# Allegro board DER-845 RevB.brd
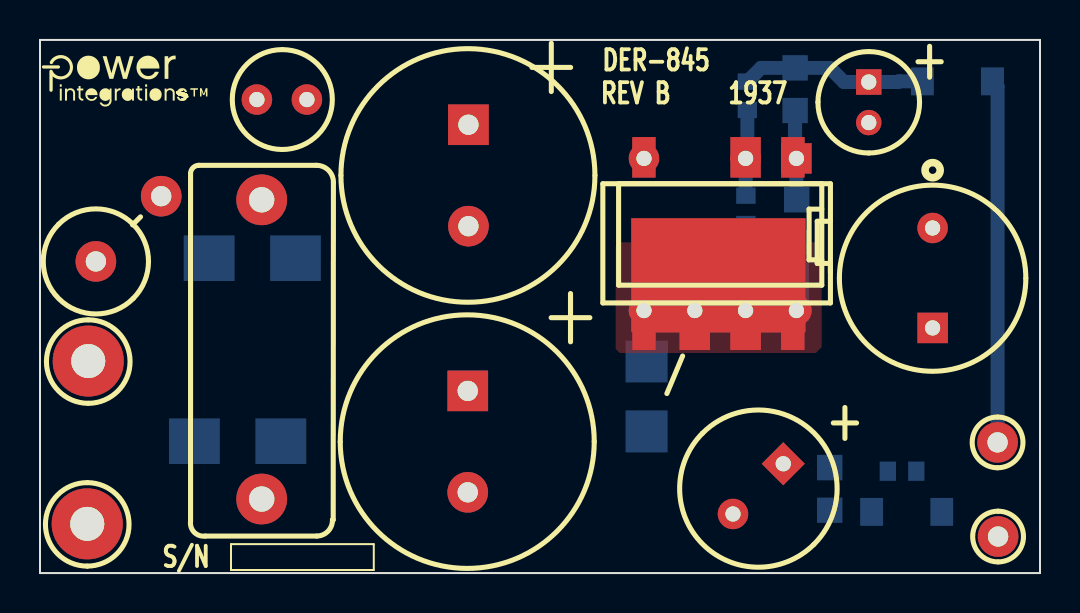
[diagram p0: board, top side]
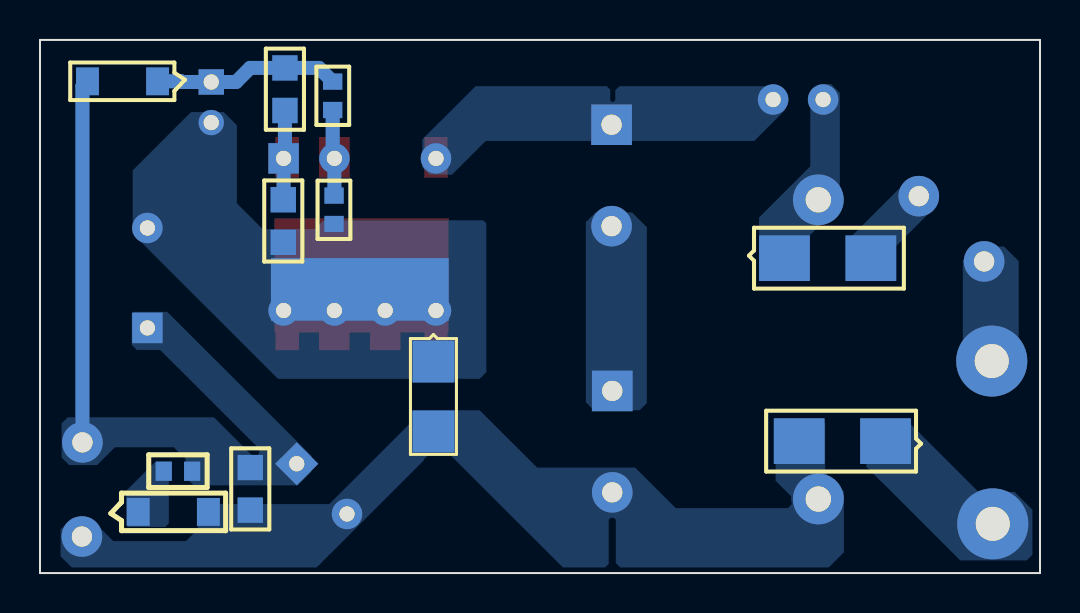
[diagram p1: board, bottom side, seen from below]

Outline 50 x 26.7 mm; copper layers: TOP, BOTTOM. Coordinates in mm from the lower left corner of the outline.
Outline path: 0,26.7 0,0 50,0 50,26.7 0,26.7

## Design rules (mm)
constraint set DEFAULT: min track width 0.508

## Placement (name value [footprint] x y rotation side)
C1  150 nF  [PI_NP_CAPRAD709X276LS590D050]  11.08 18.69 270 top
C2  47 uF  [PIPOLCAPCLYD500LS200040]  21.42 22.45 270 top
C3  100 nF  [PISMC0805]  37.84 18.7 270 bottom
C4  10 uF  [PIPOLCAPCLYD200LS80030]  41.44 24.59 270 top
C5  220 uF  [PIPOLCAPCLYD320LS140030]  37.16 5.47 225 top
C7  47 uF  [PIPOLCAPCLYD500LS200040]  21.39 9.12 270 top
D1  GS1M-LTP  [PISMDO214AC12]  12.78 15.77 180 bottom
D2  GS1M-LTP  [PISMDO214AC12]  7.72 6.61 0 bottom
D4  RS1MWF-7  [PI_SM_SOD-123_12]  44.12 24.63 0 bottom
D5  CD1408-FU1800  [PISMD1408]  30.33 10.59 270 bottom
GND  BLK  [PITPKEYSTONE100X100]  47.9 1.83 0 top
L  WHT  [PITPKEYSTONE125X125]  2.41 10.62 0 top
L1  1000 uH  [PICHOKETOKINVD216H413LS098D030]  10.85 23.71 0 top
L2  1.2 mH  [PI_CHOKE_RL5480-3_D2]  44.63 12.28 90 top
N  BLK  [PITPKEYSTONE125X125]  2.36 2.46 0 top
NOREF  -  []  -0.46 25.83 0 top
NOREF#2  -  []  0 26.7 0 top
NOREF#3  -  []  50 0 90 top
R1  2.74 k  [PISMR0603]  35.3 18.9 270 bottom
R2  18.2 k  [PISMR0603]  35.37 23.19 90 bottom
R3  35.7 k  [PISMR0805]  37.75 23.17 90 bottom
R4  24.9 k  [PISMR0805]  39.49 5.28 270 bottom
R5  499  [PISMR0603]  42.39 5.1 0 bottom
RF1  8.2  [PI2WRESD200LS725D040]  2.79 15.61 45 top
U1  LNK3296G  [PIICSMD8CSHORT5678IPC]  37.64 20.82 180 top
U2  LNK3296P  [PIICDIP8CSHORT5678]  37.82 20.77 180 top
UNK+V  RED  [PITPKEYSTONE100X100]  47.88 6.54 0 top
VR1  MMSZ5243BT1G  [PI_SM_SOD-123_12]  45.09 3.06 180 bottom

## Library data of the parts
C1 C3 = CAP NP
C2 C7 = CAP POL: alternate symbols: (pipolcapclyd500ls2000401200lh)
C4 = CAP POL: alternate symbols: (pipolcapclyd200ls80030h)
C5 = CAP POL: alternate symbols: (pipolcapclyd320ls140030430h)
D1 D2 D5 = DIODE
D4 = DIODE: alternate symbols: (pi_sm_sod-123_12_1)
GND L N UNK+V = TESTPOINT
L1 = INDUCTOR
L2 = INDUCTOR_DOT2: alternate symbols: (pi_choke_RL5480-3H_d2)
R1-R5 = R
RF1 = RF: alternate symbols: (pi2wresd200ls900d040,pi2wvresd200ls300d040,pi2wvresd200ls400d040,pi2wvresd180ls250d040,pi2wvresd180ls200d040)
U1 = LNK32XX_8C: alternate symbols: (piicsmd8cshort5678)
U2 = LNK32XX_8C
VR1 = DIODE_ZENER

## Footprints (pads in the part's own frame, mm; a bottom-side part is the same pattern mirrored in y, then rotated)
PI2WRESD200LS725D040
  round 2.032 hole 1.016: 1(0,0) 2(4.62,0)
PI_CHOKE_RL5480-3_D2
  rect 1.524x1.524 hole 0.762: 1(0,0)
  round 1.524 hole 0.762: 2(5.004,0)
PI_NP_CAPRAD709X276LS590D050
  round 2.54 hole 1.27: 1(0,0) 2(14.986,0)
PI_SM_SOD-123_12
  rect 1.143x1.397 smd: 1(0,0) 2(3.505,0)
PICHOKETOKINVD216H413LS098D030
  round 1.524 hole 0.762: 1(0,0) 2(2.5,0)
PIICDIP8CSHORT5678
  rect 1.524x1.524 hole 0.762: 1(0,0)
  round 1.524 hole 0.762: 2(2.54,0) 4(7.62,0) 5(7.62,7.62) 6(5.08,7.62) 7(2.54,7.62) 8(0,7.62)
PIICSMD8CSHORT5678IPC
  rect 1.168x2.032 smd: 1(0,0) 4(7.442,0) 5(7.442,8.636) 8(0,8.636)
  rect 1.524x2.032 smd: 2(2.362,0) 6(4.902,8.636) 7(2.362,8.636)
PIPOLCAPCLYD200LS80030
  rect 1.27x1.27 hole 0.762: 1(0,0)
  round 1.27 hole 0.762: 2(2.032,0)
PIPOLCAPCLYD320LS140030
  rect 1.524x1.524 hole 0.762: 1(0,0)
  round 1.524 hole 0.762: 2(3.556,0)
PIPOLCAPCLYD500LS200040
  rect 2.032x2.032 hole 1.016: 1(0,0)
  round 2.032 hole 1.016: 2(5.08,0)
PISMC0805
  rect 1.27x1.27 smd: 1(0,0) 2(2.134,0)
PISMD1408
  rect 2.1x2.1 smd: 1(0,0) 2(3.5,0)
PISMDO214AC12
  rect 2.54x2.286 smd: 1(0,0) 2(4.318,0)
PISMR0603
  rect 0.813x0.965 smd: 1(0,0) 2(1.422,0)
PISMR0805
  rect 1.27x1.27 smd: 1(0,0) 2(2.134,0)
PITPKEYSTONE100X100
  round 2.032 hole 1.016: 1(0,0)
PITPKEYSTONE125X125
  round 3.556 hole 1.702: 1(0,0)

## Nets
SOURCE: C3.2 C4.2 D5.1 L2.2 R1.2 U1.5(S) U1.6 U1.7 U1.8 U2.5(S) U2.6 U2.7 U2.8
N109644: C1.1 D1.1 L1.1
N109746: C2.1 L1.2 U1.4 U2.4
N109826: C1.2 C5.2 C7.2 D2.2 D5.2 GND.1 R4.2 VR1.2
N110802: C3.1 R3.1 U1.1 U2.1
N111146: R1.1 R2.1 U1.2 U2.2
N111959: C5.1 D4.2 L2.1 R4.1 R5.1 UNK+V.1
N118115: D1.2 RF1.2
N118119: L.1 RF1.1
N4132044: C4.1 D4.1 R2.2 R3.2
N4143200: D2.1 N.1
N4148852: C2.2 C7.1
N4178876: R5.2 VR1.1

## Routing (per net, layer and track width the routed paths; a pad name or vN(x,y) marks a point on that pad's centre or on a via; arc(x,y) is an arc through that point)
N110802: length 4.5
  BOTTOM w0.7: C3.1 37.82,18.71 U2.1 37.75,20.83 R3.1
N111146: length 4.3
  BOTTOM w0.7: R2.1 35.37,20.85 U2.2 35.28,18.92 R1.1
N111959: length 18.2
  BOTTOM w0.7: UNK+V.1 47.88,24.38 D4.2
N4132044: length 9.3
  BOTTOM w0.7: D4.1 42.95,24.63 42.91,24.59 C4.1 40.2,24.59 39.49,25.3 R3.2 36.05,25.3 R2.2

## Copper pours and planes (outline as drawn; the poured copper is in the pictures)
SOURCE on TOP (solid shape): 38.28,12.06 29.56,12.06 29.56,17.77 38.28,17.77
SOURCE on BOTTOM (solid shape): 38.45,12.64 29.56,12.64 29.56,15.77 38.45,15.77
SOURCE on TOP: 38.76,16.56 29.01,16.56 28.78,16.33 28.78,11.23 28.98,11.02 38.79,11.02 39.09,11.33 39.09,16.23
SOURCE on BOTTOM: 38.1,9.73 28.02,9.73 27.69,10.06 27.69,17.51 27.84,17.67 35.81,17.67 36.26,17.22 38.86,17.22 40.16,18.52 40.16,22.43 40.82,23.09 42.44,23.09 45.36,20.17 45.36,16.99
N109644 on BOTTOM: 11.48,24 11.48,20.37 14.05,17.81 14.05,14.91 11.99,14.91 11.66,15.24 11.66,16.76 10.29,18.14 10.24,18.14 10.01,18.36 10.01,24.05 10.44,24.49 11,24.49
N109746 on BOTTOM: 14.29,21.64 27.71,21.64 29.4,19.95 30.52,19.95 30.89,20.32 30.89,21.72 28.22,24.38 21.67,24.38 21.49,24.21 21.49,23.67 21.41,23.6 21.34,23.6 21.23,23.7 21.23,24.18 21.03,24.38 13.03,24.38 12.76,24.12 12.76,23.16
N109826 on BOTTOM: 10.57,0.28 20.98,0.28 21.21,0.51 21.21,2.67 21.31,2.77 21.46,2.77 21.56,2.67 21.56,0.46 21.74,0.28 23.85,0.28 29.44,5.87 30.63,5.87 30.81,5.69 30.81,5.64 36.17,0.28 48.41,0.28 48.97,0.84 48.97,2.18 48.39,2.77 47.5,2.77 46.33,1.6 42.7,1.6 42.11,2.18 42.11,3.17 41.83,3.45 35.53,3.45 31.34,7.65 31.34,8.15 28.02,8.15 25.15,5.28 20.24,5.28 18.21,3.25 12.6,3.25 12.42,3.43 12.42,3.58 12.45,3.61 12.45,3.85 13.22,4.62 13.22,7.3 12.8,7.72 10.95,7.72 10.74,7.52 10.74,5.03 9.8,4.09 9.8,1.04
N111959 on BOTTOM: 36.42,5.87 36.42,5.08 37.11,4.39 42.32,4.39 42.72,4.8 42.72,5.71 43.31,6.3 46.25,6.3 47.14,5.41 48.54,5.41 48.92,5.79 48.92,7.49 48.62,7.8 41.3,7.8 39.4,5.89 39.14,5.89 39.04,5.99 39.04,6.22 43.99,11.18 45.16,11.18 45.42,11.43 45.42,13 45.34,13.08 43.64,13.08
N118115 on BOTTOM: 5.51,19.53 5.51,18.06 7.25,16.32 7.25,15.3 7.82,14.73 9.37,14.73 9.5,14.86 9.5,16.79 6.63,19.66 5.64,19.66
N118119 on BOTTOM: 3.17,16.36 1.8,16.36 1.07,15.62 1.07,9.86 1.88,9.04 3.2,9.04 3.86,9.7 3.86,15.67
N4143200 on BOTTOM: 3.99,0.64 0.66,0.64 0.38,0.91 0.38,3.17 1.27,4.06 3.07,4.06 6.65,7.65 8.46,7.65 8.69,7.42 8.69,5.33
N4148852 on BOTTOM: 22.23,18.06 20.4,18.06 19.66,17.32 19.66,8.51 20.02,8.15 22.3,8.15 22.71,8.56 22.71,17.58
N4178876 on BOTTOM: 43.56,5.54 43.56,2.49 43.74,2.31 45.59,2.31 45.69,2.41 45.69,4.11 44.27,5.54

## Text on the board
Ref Des/Silkscreen Top: S/N | REV B | DER-845 | 1937
User.5: 1.  THROUGH HOLES ARE PLATED THROUGH. | EXCEPTIONS WILL BE NOTED IN DRILL CHART "NOTE". | 2.  MATERIAL: BASE MATERIAL LAMINATED EPOXY | UL APPROVED MANUFACTURED SOURCE FOR FR4. | 3.  SOLDER PLATE WILL BE RoHS COMPLIANT. | 4.  SOLDER MASK LPI (LIQUID PHOTO IMAGEABLE) BOTH SIDES. COLOR GREEN. | SOLDER MASK (REGISTRATION) -0/+0.003" | 5.  SILKSCREEN TOP/BOTTOM SIDE. COLOR WHITE. (MIN.WIDTH 0.005" MAX.WIDTH 0.010") | 6.  FINISH TO BE SMOBC. | 7.  LEAD FREE HASL (HOT AIR SOLDER LEVEL) OR RoHS COMPLIANT. | 8.  BOARD DIMENSION +/- 0.005" | 9.  DRILL TOLERANCE +/- 0.003" | 10. TRACE WIDTH UNDER 0.010" +/- 0.002" | TRACE WIDTH OVER 0.011" +/- 0.005" | 11. TRACE SPACE +/- 0.003" | 12. MATERIAL FR4 COPPER 1 OZ BOARD THICKNESS 0.039" | NOTES: UNLESS OTHERWISE SPECIFIED
User.8: FIGURE | FINISHED_SIZE | 30.0 | 40.0 | 50.0 | 67.0 | DRILL CHART: TOP to BOTTOM | ALL UNITS ARE IN MILS | PLATED | QTY | 15 | 4 | 2
